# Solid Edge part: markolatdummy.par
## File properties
Author: morva
Template: iso metric part.par
Last saved by: morva
Revision: 3
Application: Solid Edge
Username: morva
Accuracy: 0.990
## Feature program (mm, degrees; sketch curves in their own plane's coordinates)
sketch for "unnamed Protrusion 1" #1 plane through (0, 0, 0) normal (0, 0, 1) x-axis (1, 0, 0)
  circle centre (0, 0) radius 11
sketch for "unnamed Protrusion 1" #2 plane through (0, 0, 0) normal (0, 0, 1) x-axis (1, 0, 0)
  circle centre (0, 0) radius 14
extrude "unnamed Protrusion 1" add finite 110 symmetric
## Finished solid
Body 1: solid body, 4 faces, 4 edges, 0 vertices.
  Faces by surface: cylinder 2, plane 2
  Edges by curve: circle 4
Bounding box of the edges (mm): 28.000 x 28.000 x 110.000, from (-14, -14, -55) to (14, 14, 55).
Cylindrical faces by radius (mm): R11 x1, R14 x1
Planar faces by outward normal: +z 1, -z 1
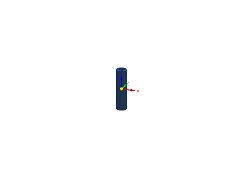
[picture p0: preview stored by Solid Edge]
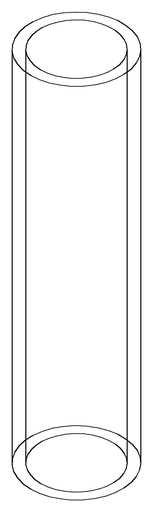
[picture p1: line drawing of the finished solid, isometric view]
